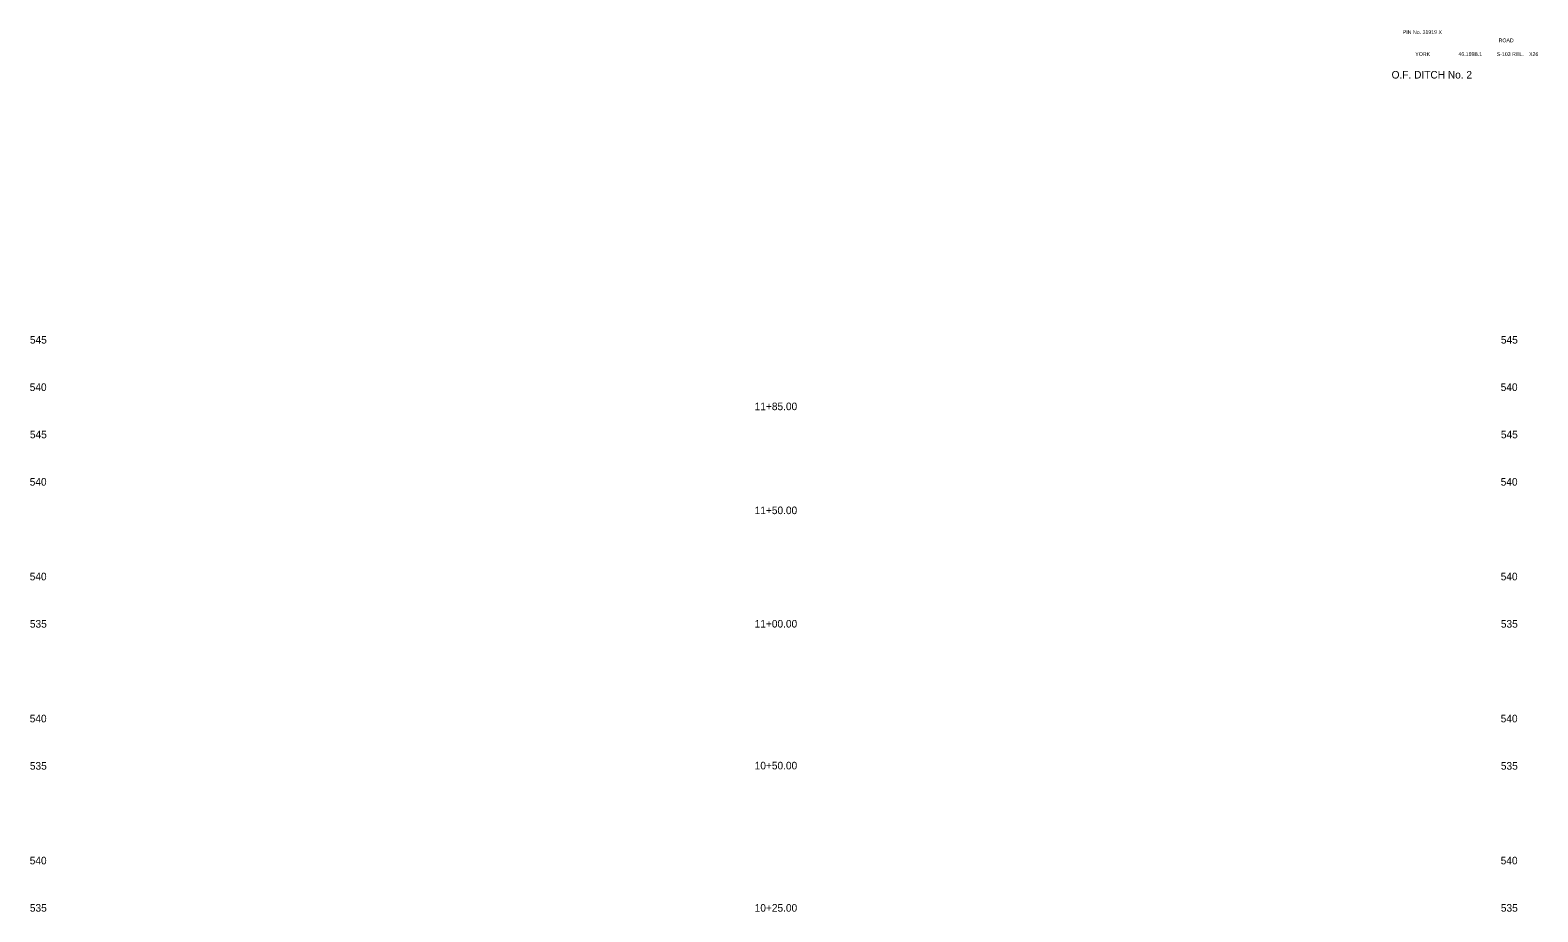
# Model space of a CAD drawing. Extents: x 1001 to 1161, y 1010 to 1103.
import ezdxf

# ---------------------------------------------------------------- set-up
doc = ezdxf.new("R2010")
doc.units = 0
for name, color, linetype in [('RD_SHT_TX', 7, 'Continuous'), ('RD_XS_TX_Elev_EX', 7, 'Continuous'), ('RD_XS_TX_Station', 7, 'Continuous')]:
    doc.layers.add(name, color=color, linetype=linetype)

msp = doc.modelspace()

# ---------------------------------------------------------------- texts
at = {"layer": 'RD_SHT_TX'}
for s, height, p in [('PIN No. 31919 X', 0.4, (1146.28, 1102.8)), ('ROAD', 0.4, (1156.41, 1101.93)), ('YORK', 0.4, (1147.6, 1100.48)), ('46.169B.1', 0.4, (1152.16, 1100.48)), ('S-103 REL.', 0.4, (1156.21, 1100.48)), ('X26', 0.4, (1159.63, 1100.48)), ('O.F. DITCH No. 2', 0.8, (1145.1, 1098.1))]:
    msp.add_text(s, height=height, dxfattribs=at).set_placement(p)
at = {"layer": 'RD_XS_TX_Elev_EX'}
for s, p in [('545', (1001.15, 1070.1)), ('545', (1156.65, 1070.1)), ('540', (1001.13, 1065.1)), ('540', (1156.63, 1065.1)), ('545', (1001.15, 1060.1)), ('545', (1156.65, 1060.1)), ('540', (1001.13, 1055.1)), ('540', (1156.63, 1055.1)), ('540', (1001.13, 1045.1)), ('540', (1156.63, 1045.1)), ('535', (1001.15, 1040.1)), ('535', (1156.65, 1040.1)), ('540', (1001.13, 1030.1)), ('540', (1156.63, 1030.1)), ('535', (1001.15, 1025.1)), ('535', (1156.65, 1025.1)), ('540', (1001.13, 1015.1)), ('540', (1156.63, 1015.1)), ('535', (1001.15, 1010.1)), ('535', (1156.65, 1010.1))]:
    msp.add_text(s, height=0.8, dxfattribs=at).set_placement(p)
at = {"layer": 'RD_XS_TX_Station'}
for s, p in [('11+85.00', (1077.77, 1063.07)), ('11+50.00', (1077.77, 1052.09)), ('11+00.00', (1077.77, 1040.11)), ('10+50.00', (1077.77, 1025.13)), ('10+25.00', (1077.77, 1010.1))]:
    msp.add_text(s, height=0.8, dxfattribs=at).set_placement(p)

doc.saveas('drawing.dxf')
